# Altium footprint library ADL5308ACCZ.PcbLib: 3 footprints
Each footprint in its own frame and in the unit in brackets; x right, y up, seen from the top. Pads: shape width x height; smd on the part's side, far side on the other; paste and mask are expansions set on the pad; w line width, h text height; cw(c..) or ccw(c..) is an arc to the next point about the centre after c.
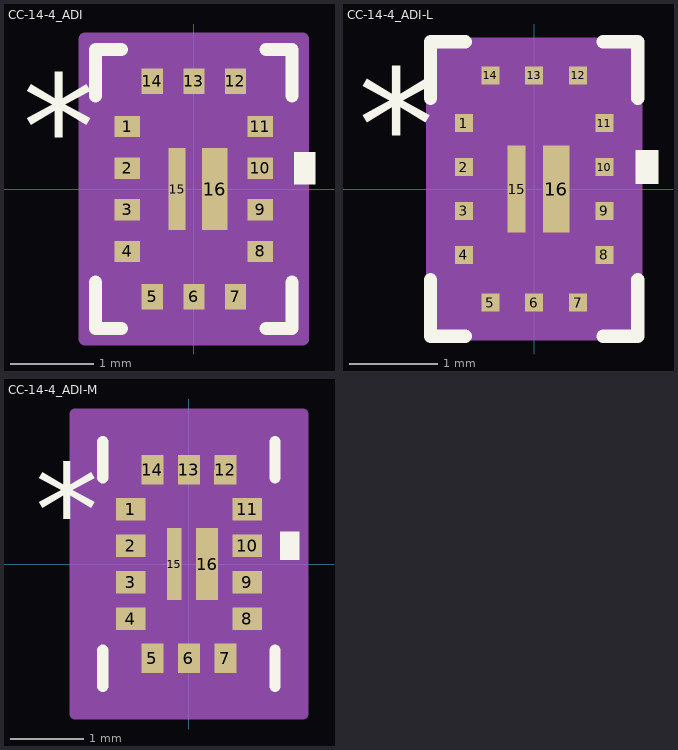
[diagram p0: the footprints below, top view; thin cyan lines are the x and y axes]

## CC-14-4_ADI [mil]
pads (16):
  rect 12x10 smd paste+0 mask+0: 1(-31.5,29.53) 2(-31.5,9.84) 3(-31.5,-9.84) 4(-31.5,-29.53) 8(31.5,-29.53) 9(31.5,-9.84) 10(31.5,9.84) 11(31.5,29.53)
  rect 10x12 smd paste+0 mask+0: 5(-19.68,-51) 6(0,-51) 7(19.68,-51) 12(19.68,51) 13(0,51) 14(-19.68,51)
  rect 8x39 smd paste+0 mask+0: 15(-7.87,0)
  rect 12x39 smd paste+0 mask+0: 16(9.84,0)
Top Overlay:
  region: 47.5,17.34 57.5,17.34 57.5,2.34 47.5,2.34
  lines w6: -46.5,-44.05 -46.5,-66 -34.2,-66 ; -46.5,44.05 -46.5,66 -34.2,66 ; 34.2,-66 46.5,-66 46.5,-44.05 ; 34.2,66 46.5,66 46.5,44.05
  text "*" at -81,4.53 h50
  text ".Designator" at -137.5,-25 h50
Mechanical 13:
  lines w1: -41.5,11 8.5,61 ; -41.5,-61 41.5,-61 41.5,61 -41.5,61 -41.5,-61 ; -41.5,-34.53 -41.5,-24.53 -37.5,-24.53 -37.5,-34.53 -41.5,-34.53 ; -41.5,-14.84 -41.5,-4.84 -37.5,-4.84 -37.5,-14.84 -41.5,-14.84 ; -41.5,4.84 -41.5,14.84 -37.5,14.84 -37.5,4.84 -41.5,4.84 ; -41.5,24.53 -41.5,34.53 -37.5,34.53 -37.5,24.53 -41.5,24.53 ; -24.68,-61 -14.69,-61 -14.69,-57 -24.68,-57 -24.68,-61 ; -24.68,57 -14.69,57 -14.69,61 -24.68,61 -24.68,57 ; -5,-61 5,-61 5,-57 -5,-57 -5,-61 ; -5,57 5,57 5,61 -5,61 -5,57 ; 14.69,-61 24.68,-61 24.68,-57 14.69,-57 14.69,-61 ; 14.69,57 24.68,57 24.68,61 14.69,61 14.69,57 ; 37.5,-34.53 41.5,-34.53 41.5,-24.53 37.5,-24.53 37.5,-34.53 ; 37.5,-14.84 41.5,-14.84 41.5,-4.84 37.5,-4.84 37.5,-14.84 ; 37.5,4.84 41.5,4.84 41.5,14.84 37.5,14.84 37.5,4.84 ; 37.5,24.53 41.5,24.53 41.5,34.53 37.5,34.53 37.5,24.53
  text ".Designator" at -137.5,-25 h50
  text "*" at -7,4.53 h50
Mechanical 15:
  region: -34.69,-71 -51.5,-71 -51.5,-44.53 -51.5,44.53 -51.5,71 -34.69,71 34.69,71 51.5,71 51.5,44.53 51.5,-44.53 51.5,-71 34.69,-71
  lines w6: -51.5,-44.53 -51.5,-71 -34.69,-71 ; -51.5,-44.53 -51.5,-44.53 ; -51.5,-44.53 -51.5,44.53 ; -51.5,44.53 -51.5,44.53 ; -51.5,44.53 -51.5,71 -34.69,71 ; -34.69,-71 34.69,-71 ; -34.69,-71 -34.69,-71 ; -34.69,71 -34.69,71 ; -34.69,71 34.69,71 ; 34.69,-71 51.5,-71 51.5,-44.53 ; 34.69,-71 34.69,-71 ; 34.69,71 34.69,71 ; 34.69,71 51.5,71 51.5,44.53 ; 51.5,-44.53 51.5,44.53 ; 51.5,-44.53 51.5,-44.53 ; 51.5,44.53 51.5,44.53
3D body "CC-14-4_ADI.step": height 29.09, standoff 0, extent -41.5,-60.98 41.5,60.98

## CC-14-4_ADI-L [mil]
pads (16):
  rect 8.06x8.03 smd paste+0 mask+0: 1(-31.5,29.53) 2(-31.5,9.84) 3(-31.5,-9.84) 4(-31.5,-29.53) 8(31.5,-29.53) 9(31.5,-9.84) 10(31.5,9.84) 11(31.5,29.53)
  rect 8.03x8.06 smd paste+0 mask+0: 5(-19.68,-51) 6(0,-51) 7(19.68,-51) 12(19.68,51) 13(0,51) 14(-19.68,51)
  rect 8x39 smd paste+0 mask+0: 15(-7.87,0)
  rect 12x39 smd paste+0 mask+0: 16(9.84,0)
Top Overlay:
  region: 45.53,17.34 55.53,17.34 55.53,2.34 45.53,2.34
  lines w6: -46.5,-40.71 -46.5,-66 -30.86,-66 ; -46.5,40.71 -46.5,66 -30.86,66 ; 30.86,-66 46.5,-66 46.5,-40.71 ; 30.86,66 46.5,66 46.5,40.71
  text "*" at -79.03,4.53 h50
  text ".Designator" at -137.5,-25 h50
Mechanical 13:
  lines w1: -41.5,11 8.5,61 ; -41.5,-61 41.5,-61 41.5,61 -41.5,61 -41.5,-61 ; -41.5,-34.53 -41.5,-24.53 -37.5,-24.53 -37.5,-34.53 -41.5,-34.53 ; -41.5,-14.84 -41.5,-4.84 -37.5,-4.84 -37.5,-14.84 -41.5,-14.84 ; -41.5,4.84 -41.5,14.84 -37.5,14.84 -37.5,4.84 -41.5,4.84 ; -41.5,24.53 -41.5,34.53 -37.5,34.53 -37.5,24.53 -41.5,24.53 ; -24.68,-61 -14.69,-61 -14.69,-57 -24.68,-57 -24.68,-61 ; -24.68,57 -14.69,57 -14.69,61 -24.68,61 -24.68,57 ; -5,-61 5,-61 5,-57 -5,-57 -5,-61 ; -5,57 5,57 5,61 -5,61 -5,57 ; 14.69,-61 24.68,-61 24.68,-57 14.69,-57 14.69,-61 ; 14.69,57 24.68,57 24.68,61 14.69,61 14.69,57 ; 37.5,-34.53 41.5,-34.53 41.5,-24.53 37.5,-24.53 37.5,-34.53 ; 37.5,-14.84 41.5,-14.84 41.5,-4.84 37.5,-4.84 37.5,-14.84 ; 37.5,4.84 41.5,4.84 41.5,14.84 37.5,14.84 37.5,4.84 ; 37.5,24.53 41.5,24.53 41.5,34.53 37.5,34.53 37.5,24.53
  text ".Designator" at -137.5,-25 h50
  text "*" at -8.97,4.53 h50
Mechanical 15:
  region: -27.7,-65 -45.5,-65 -45.5,-37.54 -45.5,37.54 -45.5,65 -27.7,65 27.7,65 45.5,65 45.5,37.54 45.5,-37.54 45.5,-65 27.7,-65
  lines w6: -45.5,-37.54 -45.5,-65 -27.7,-65 ; -45.5,-37.54 -45.5,-37.54 ; -45.5,-37.54 -45.5,37.54 ; -45.5,37.54 -45.5,37.54 ; -45.5,37.54 -45.5,65 -27.7,65 ; -27.7,-65 27.7,-65 ; -27.7,-65 -27.7,-65 ; -27.7,65 -27.7,65 ; -27.7,65 27.7,65 ; 27.7,-65 45.5,-65 45.5,-37.54 ; 27.7,-65 27.7,-65 ; 27.7,65 27.7,65 ; 27.7,65 45.5,65 45.5,37.54 ; 45.5,-37.54 45.5,37.54 ; 45.5,-37.54 45.5,-37.54 ; 45.5,37.54 45.5,37.54
3D body "CC-14-4_ADI.step": height 29.09, standoff 0, extent -41.5,-60.98 41.5,60.98

## CC-14-4_ADI-M [mil]
pads (16):
  rect 15.94x11.97 smd paste+0 mask+0: 1(-31.5,29.53) 2(-31.5,9.84) 3(-31.5,-9.84) 4(-31.5,-29.53) 8(31.5,-29.53) 9(31.5,-9.84) 10(31.5,9.84) 11(31.5,29.53)
  rect 11.97x15.94 smd paste+0 mask+0: 5(-19.68,-51) 6(0,-51) 7(19.68,-51) 12(19.68,51) 13(0,51) 14(-19.68,51)
  rect 8x39 smd paste+0 mask+0: 15(-7.87,0)
  rect 12x39 smd paste+0 mask+0: 16(9.84,0)
Top Overlay:
  region: 49.47,17.34 59.47,17.34 59.47,2.34 49.47,2.34
  lines w6: -46.5,-66 -46.5,-46.56 ; -46.5,46.56 -46.5,66 ; 46.5,-66 46.5,-46.56 ; 46.5,46.56 46.5,66
  text "*" at -82.97,4.53 h50
  text ".Designator" at -137.5,-25 h50
Mechanical 13:
  lines w1: -41.5,11 8.5,61 ; -41.5,-61 41.5,-61 41.5,61 -41.5,61 -41.5,-61 ; -41.5,-34.53 -41.5,-24.53 -37.5,-24.53 -37.5,-34.53 -41.5,-34.53 ; -41.5,-14.84 -41.5,-4.84 -37.5,-4.84 -37.5,-14.84 -41.5,-14.84 ; -41.5,4.84 -41.5,14.84 -37.5,14.84 -37.5,4.84 -41.5,4.84 ; -41.5,24.53 -41.5,34.53 -37.5,34.53 -37.5,24.53 -41.5,24.53 ; -24.68,-61 -14.69,-61 -14.69,-57 -24.68,-57 -24.68,-61 ; -24.68,57 -14.69,57 -14.69,61 -24.68,61 -24.68,57 ; -5,-61 5,-61 5,-57 -5,-57 -5,-61 ; -5,57 5,57 5,61 -5,61 -5,57 ; 14.69,-61 24.68,-61 24.68,-57 14.69,-57 14.69,-61 ; 14.69,57 24.68,57 24.68,61 14.69,61 14.69,57 ; 37.5,-34.53 41.5,-34.53 41.5,-24.53 37.5,-24.53 37.5,-34.53 ; 37.5,-14.84 41.5,-14.84 41.5,-4.84 37.5,-4.84 37.5,-14.84 ; 37.5,4.84 41.5,4.84 41.5,14.84 37.5,14.84 37.5,4.84 ; 37.5,24.53 41.5,24.53 41.5,34.53 37.5,34.53 37.5,24.53
  text ".Designator" at -137.5,-25 h50
  text "*" at -5.03,4.53 h50
Mechanical 15:
  region: -45.67,-81 -61.5,-81 -61.5,-55.51 -61.5,55.51 -61.5,81 -45.67,81 45.67,81 61.5,81 61.5,55.51 61.5,-55.51 61.5,-81 45.67,-81
  lines w6: -61.5,-55.51 -61.5,-81 -45.67,-81 ; -61.5,-55.51 -61.5,-55.51 ; -61.5,-55.51 -61.5,55.51 ; -61.5,55.51 -61.5,55.51 ; -61.5,55.51 -61.5,81 -45.67,81 ; -45.67,-81 45.67,-81 ; -45.67,-81 -45.67,-81 ; -45.67,81 -45.67,81 ; -45.67,81 45.67,81 ; 45.67,-81 61.5,-81 61.5,-55.51 ; 45.67,-81 45.67,-81 ; 45.67,81 45.67,81 ; 45.67,81 61.5,81 61.5,55.51 ; 61.5,-55.51 61.5,55.51 ; 61.5,-55.51 61.5,-55.51 ; 61.5,55.51 61.5,55.51
3D body "CC-14-4_ADI.step": height 29.09, standoff 0, extent -41.5,-60.98 41.5,60.98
